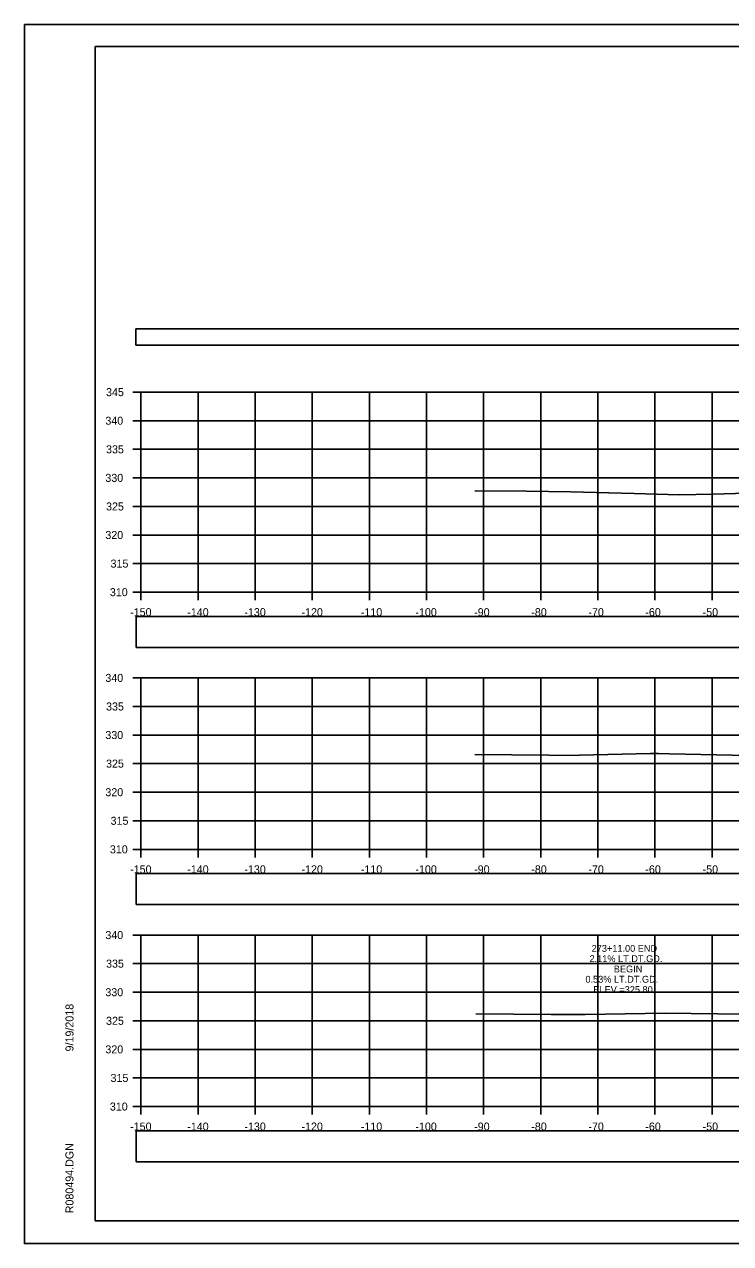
# Model space of a CAD drawing. Extents: x 1376273 to 1384221, y 378927 to 384592.
# Drawn here: x 1380021.2 to 1380144.9, y 383525.2 to 383738.6 of the extents above; entities that cross this region are included whole.
import ezdxf

# ---------------------------------------------------------------- set-up
doc = ezdxf.new("R2010")
doc.units = 0
for name, color, linetype in [('R_Axis', 7, 'Continuous'), ('R_Axis Annot', 7, 'Continuous'), ('R_Border', 7, 'Continuous'), ('R_Exist Surface', 7, 'Continuous'), ('R_Grid', 7, 'Continuous'), ('R_No Plot', 7, 'Continuous'), ('R_Xsect Elev', 7, 'Continuous')]:
    doc.layers.add(name, color=color, linetype=linetype)

msp = doc.modelspace()

# ---------------------------------------------------------------- linework, layer by layer
at = {"layer": 'R_Axis'}
for p, q in [((1380040.26, 383674.23), (1380041.66, 383674.23)), ((1380041.66, 383639.23), (1380041.66, 383674.23)), ((1380040.26, 383669.23), (1380041.66, 383669.23)), ((1380040.26, 383664.23), (1380041.66, 383664.23)), ((1380040.26, 383659.23), (1380041.66, 383659.23)), ((1380040.26, 383654.23), (1380041.66, 383654.23)), ((1380040.26, 383649.23), (1380041.66, 383649.23)), ((1380040.26, 383644.23), (1380041.66, 383644.23)), ((1380040.26, 383639.23), (1380041.66, 383639.23)), ((1380041.66, 383639.23), (1380341.66, 383639.23)), ((1380041.66, 383637.83), (1380041.66, 383639.23)), ((1380051.66, 383637.83), (1380051.66, 383639.23)), ((1380061.66, 383637.83), (1380061.66, 383639.23)), ((1380071.66, 383637.83), (1380071.66, 383639.23)), ((1380081.66, 383637.83), (1380081.66, 383639.23)), ((1380091.66, 383637.83), (1380091.66, 383639.23)), ((1380101.66, 383637.83), (1380101.66, 383639.23)), ((1380111.66, 383637.83), (1380111.66, 383639.23)), ((1380121.66, 383637.83), (1380121.66, 383639.23)), ((1380131.66, 383637.83), (1380131.66, 383639.23)), ((1380141.66, 383637.83), (1380141.66, 383639.23)), ((1380040.26, 383624.23), (1380041.66, 383624.23)), ((1380041.66, 383594.23), (1380041.66, 383624.23)), ((1380040.26, 383619.23), (1380041.66, 383619.23)), ((1380040.26, 383614.23), (1380041.66, 383614.23)), ((1380040.26, 383609.23), (1380041.66, 383609.23)), ((1380040.26, 383604.23), (1380041.66, 383604.23)), ((1380040.26, 383599.23), (1380041.66, 383599.23)), ((1380040.26, 383594.23), (1380041.66, 383594.23)), ((1380041.66, 383594.23), (1380341.66, 383594.23)), ((1380041.66, 383592.83), (1380041.66, 383594.23)), ((1380051.66, 383592.83), (1380051.66, 383594.23)), ((1380061.66, 383592.83), (1380061.66, 383594.23)), ((1380071.66, 383592.83), (1380071.66, 383594.23)), ((1380081.66, 383592.83), (1380081.66, 383594.23)), ((1380091.66, 383592.83), (1380091.66, 383594.23)), ((1380101.66, 383592.83), (1380101.66, 383594.23)), ((1380111.66, 383592.83), (1380111.66, 383594.23)), ((1380121.66, 383592.83), (1380121.66, 383594.23)), ((1380131.66, 383592.83), (1380131.66, 383594.23)), ((1380141.66, 383592.83), (1380141.66, 383594.23)), ((1380040.26, 383579.23), (1380041.66, 383579.23)), ((1380041.66, 383549.23), (1380041.66, 383579.23)), ((1380040.26, 383574.23), (1380041.66, 383574.23)), ((1380040.26, 383569.23), (1380041.66, 383569.23)), ((1380040.26, 383564.23), (1380041.66, 383564.23)), ((1380040.26, 383559.23), (1380041.66, 383559.23)), ((1380040.26, 383554.23), (1380041.66, 383554.23)), ((1380040.26, 383549.23), (1380041.66, 383549.23)), ((1380041.66, 383549.23), (1380341.66, 383549.23)), ((1380041.66, 383547.83), (1380041.66, 383549.23)), ((1380051.66, 383547.83), (1380051.66, 383549.23)), ((1380061.66, 383547.83), (1380061.66, 383549.23)), ((1380071.66, 383547.83), (1380071.66, 383549.23)), ((1380081.66, 383547.83), (1380081.66, 383549.23)), ((1380091.66, 383547.83), (1380091.66, 383549.23)), ((1380101.66, 383547.83), (1380101.66, 383549.23)), ((1380111.66, 383547.83), (1380111.66, 383549.23)), ((1380121.66, 383547.83), (1380121.66, 383549.23)), ((1380131.66, 383547.83), (1380131.66, 383549.23)), ((1380141.66, 383547.83), (1380141.66, 383549.23))]:
    msp.add_line(p, q, dxfattribs=at)
at = {"layer": 'R_Axis Annot'}
for points in [[(1380040.77, 383682.47), (1380342.57, 383682.47), (1380342.57, 383685.29), (1380040.77, 383685.29)], [(1380040.81, 383629.56), (1380342.5, 383629.56), (1380342.5, 383634.97), (1380040.81, 383634.97)], [(1380040.81, 383584.57), (1380342.5, 383584.57), (1380342.5, 383589.98), (1380040.81, 383589.98)], [(1380040.81, 383539.58), (1380342.5, 383539.58), (1380342.5, 383544.99), (1380040.81, 383544.99)]]:
    msp.add_lwpolyline(points, close=True, dxfattribs=at)
at = {"layer": 'R_Border'}
for p, q in [((1380033.66, 383734.69), (1380349.84, 383734.69)), ((1380033.66, 383529.23), (1380033.66, 383734.69)), ((1380033.66, 383529.23), (1380033.66, 383529.23)), ((1380349.84, 383529.23), (1380033.66, 383529.23))]:
    msp.add_line(p, q, dxfattribs=at)
at = {"layer": 'R_Exist Surface'}
for points in [[(1380100.11, 383656.91), (1380100.39, 383656.95), (1380109.16, 383656.88), (1380116.9, 383656.77), (1380127.99, 383656.48), (1380135.97, 383656.29), (1380141.71, 383656.39), (1380147.8, 383656.58)], [(1380100.09, 383610.83), (1380113.09, 383610.7), (1380115.95, 383610.68), (1380130.86, 383610.99), (1380132.29, 383611.01), (1380134.2, 383610.97), (1380147.9, 383610.63)], [(1380100.29, 383565.43), (1380113.51, 383565.36), (1380116.63, 383565.31), (1380119.46, 383565.35), (1380133.42, 383565.57), (1380147.15, 383565.41)]]:
    msp.add_lwpolyline(points, dxfattribs=at)
at = {"layer": 'R_Grid'}
for p, q in [((1380041.66, 383674.23), (1380341.66, 383674.23)), ((1380041.66, 383639.23), (1380041.66, 383674.23)), ((1380051.66, 383639.23), (1380051.66, 383674.23)), ((1380061.66, 383639.23), (1380061.66, 383674.23)), ((1380071.66, 383639.23), (1380071.66, 383674.23)), ((1380081.66, 383639.23), (1380081.66, 383674.23)), ((1380091.66, 383639.23), (1380091.66, 383674.23)), ((1380101.66, 383639.23), (1380101.66, 383674.23)), ((1380111.66, 383639.23), (1380111.66, 383674.23)), ((1380121.66, 383639.23), (1380121.66, 383674.23)), ((1380131.66, 383639.23), (1380131.66, 383674.23)), ((1380141.66, 383639.23), (1380141.66, 383674.23)), ((1380041.66, 383669.23), (1380341.66, 383669.23)), ((1380041.66, 383664.23), (1380341.66, 383664.23)), ((1380041.66, 383659.23), (1380341.66, 383659.23)), ((1380041.66, 383654.23), (1380341.66, 383654.23)), ((1380041.66, 383649.23), (1380341.66, 383649.23)), ((1380041.66, 383644.23), (1380341.66, 383644.23)), ((1380041.66, 383639.23), (1380341.66, 383639.23)), ((1380041.66, 383624.23), (1380341.66, 383624.23)), ((1380041.66, 383594.23), (1380041.66, 383624.23)), ((1380051.66, 383594.23), (1380051.66, 383624.23)), ((1380061.66, 383594.23), (1380061.66, 383624.23)), ((1380071.66, 383594.23), (1380071.66, 383624.23)), ((1380081.66, 383594.23), (1380081.66, 383624.23)), ((1380091.66, 383594.23), (1380091.66, 383624.23)), ((1380101.66, 383594.23), (1380101.66, 383624.23)), ((1380111.66, 383594.23), (1380111.66, 383624.23)), ((1380121.66, 383594.23), (1380121.66, 383624.23)), ((1380131.66, 383594.23), (1380131.66, 383624.23)), ((1380141.66, 383594.23), (1380141.66, 383624.23)), ((1380041.66, 383619.23), (1380341.66, 383619.23)), ((1380041.66, 383614.23), (1380341.66, 383614.23)), ((1380041.66, 383609.23), (1380341.66, 383609.23)), ((1380041.66, 383604.23), (1380341.66, 383604.23)), ((1380041.66, 383599.23), (1380341.66, 383599.23)), ((1380041.66, 383594.23), (1380341.66, 383594.23)), ((1380041.66, 383579.23), (1380341.66, 383579.23)), ((1380041.66, 383549.23), (1380041.66, 383579.23)), ((1380051.66, 383549.23), (1380051.66, 383579.23)), ((1380061.66, 383549.23), (1380061.66, 383579.23)), ((1380071.66, 383549.23), (1380071.66, 383579.23)), ((1380081.66, 383549.23), (1380081.66, 383579.23)), ((1380091.66, 383549.23), (1380091.66, 383579.23)), ((1380101.66, 383549.23), (1380101.66, 383579.23)), ((1380111.66, 383549.23), (1380111.66, 383579.23)), ((1380121.66, 383549.23), (1380121.66, 383579.23)), ((1380131.66, 383549.23), (1380131.66, 383579.23)), ((1380141.66, 383549.23), (1380141.66, 383579.23)), ((1380041.66, 383574.23), (1380341.66, 383574.23)), ((1380041.66, 383569.23), (1380341.66, 383569.23)), ((1380041.66, 383564.23), (1380341.66, 383564.23)), ((1380041.66, 383559.23), (1380341.66, 383559.23)), ((1380041.66, 383554.23), (1380341.66, 383554.23)), ((1380041.66, 383549.23), (1380341.66, 383549.23))]:
    msp.add_line(p, q, dxfattribs=at)
at = {"layer": 'R_No Plot'}
for p, q in [((1380021.26, 383738.58), (1380354.59, 383738.58)), ((1380021.26, 383525.25), (1380354.59, 383525.25))]:
    msp.add_line(p, q, dxfattribs=at)
for points in [[(1380021.25, 383738.58), (1380354.59, 383738.58), (1380354.59, 383525.24), (1380021.25, 383525.24)], [(1380267.58, 383734.69), (1380267.58, 383724.81), (1380303.31, 383724.81), (1380303.31, 383721.89), (1380326.51, 383721.89), (1380326.51, 383697.55), (1380349.84, 383697.55), (1380349.84, 383529.23), (1380033.66, 383529.23), (1380033.66, 383734.69)]]:
    msp.add_lwpolyline(points, close=True, dxfattribs=at)

# ---------------------------------------------------------------- texts
at = {"layer": 'R_Axis Annot'}
for s, p in [('345', (1380035.55, 383673.53)), ('340', (1380035.43, 383668.53)), ('335', (1380035.55, 383663.53)), ('330', (1380035.43, 383658.53)), ('325', (1380035.55, 383653.53)), ('320', (1380035.43, 383648.53)), ('315', (1380036.34, 383643.53)), ('310', (1380036.22, 383638.53)), ('-150', (1380039.77, 383635.03)), ('-140', (1380049.77, 383635.03)), ('-130', (1380059.77, 383635.03)), ('-120', (1380069.77, 383635.03)), ('-110', (1380080.16, 383635.03)), ('-100', (1380089.71, 383635.03)), ('-90', (1380100, 383635.03)), ('-80', (1380110, 383635.03)), ('-70', (1380120, 383635.03)), ('-60', (1380129.97, 383635.03)), ('-50', (1380140, 383635.03)), ('340', (1380035.43, 383623.53)), ('335', (1380035.55, 383618.53)), ('330', (1380035.43, 383613.53)), ('325', (1380035.55, 383608.53)), ('320', (1380035.43, 383603.53)), ('315', (1380036.34, 383598.53)), ('310', (1380036.22, 383593.53)), ('-150', (1380039.77, 383590.03)), ('-140', (1380049.77, 383590.03)), ('-130', (1380059.77, 383590.03)), ('-120', (1380069.77, 383590.03)), ('-110', (1380080.16, 383590.03)), ('-100', (1380089.71, 383590.03)), ('-90', (1380100, 383590.03)), ('-80', (1380110, 383590.03)), ('-70', (1380120, 383590.03)), ('-60', (1380129.97, 383590.03)), ('-50', (1380140, 383590.03)), ('340', (1380035.43, 383578.53)), ('335', (1380035.55, 383573.53)), ('330', (1380035.43, 383568.53)), ('325', (1380035.55, 383563.53)), ('320', (1380035.43, 383558.53)), ('315', (1380036.34, 383553.53)), ('310', (1380036.22, 383548.53)), ('-150', (1380039.77, 383545.03)), ('-140', (1380049.77, 383545.03)), ('-130', (1380059.77, 383545.03)), ('-120', (1380069.77, 383545.03)), ('-110', (1380080.16, 383545.03)), ('-100', (1380089.71, 383545.03)), ('-90', (1380100, 383545.03)), ('-80', (1380110, 383545.03)), ('-70', (1380120, 383545.03)), ('-60', (1380129.97, 383545.03)), ('-50', (1380140, 383545.03))]:
    msp.add_text(s, height=1.4, dxfattribs=at).set_placement(p)
at = {"layer": 'R_Border'}
for s, p in [('9/19/2018', (1380029.85, 383558.87)), ('R080494.DGN', (1380029.85, 383530.55))]:
    msp.add_text(s, height=1.4, rotation=90, dxfattribs=at).set_placement(p)
at = {"layer": 'R_Xsect Elev'}
for s, p in [('273+11.00 END', (1380120.57, 383576.3)), ('2.11% LT.DT.GD.', (1380120.2, 383574.5)), ('BEGIN', (1380124.45, 383572.7)), ('0.53% LT.DT.GD.', (1380119.48, 383570.9)), ('ELEV.=325.80', (1380120.87, 383569.1))]:
    msp.add_text(s, height=1.2, rotation=360, dxfattribs=at).set_placement(p)

doc.saveas('drawing.dxf')
